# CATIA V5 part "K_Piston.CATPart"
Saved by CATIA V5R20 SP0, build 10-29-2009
Part number: Piston
Bounding box of the stored display mesh (mm): x -48 to -28, y 164.401 to 194.581, z -165.022 to -124.41
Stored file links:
  G:\Khaled_CFAO_2011\ST2M\ST2M_GR2\plakomicki\Khaled\CAD_ThinkMOTION\K_Piston.CATPart
  G:\Khaled_CFAO_2011\ST2M\ST2M_GR2\plakomicki\Khaled\CAD_ThinkMOTION\K_Jambe.CATProduct
  G:\Khaled_CFAO_2011\ST2M\ST2M_GR2\plakomicki\Khaled\plakomicki\Squelette_balancier.CATPart
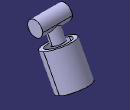
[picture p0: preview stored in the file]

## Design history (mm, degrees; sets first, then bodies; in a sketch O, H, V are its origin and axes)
Set1
  Plane1: linked copy from another document
  Point1: linked copy from another document
  Plane2: linked copy from another document
  Point2: linked copy from another document
Body1 (main body)
  Sketch1 on Plane1, origin (-38, 0, 0), H (0, 1, 0), V (0, 0, 1)
    circle A1 centre (169.4005, -129.4005) radius 5
    point P1 (169.4005, -129.4005)
    reference projected point E1 (169.4005, -129.4005) from Point1
    radius A1 = 5
    coincidence: P1 E1
  Pad1: profile Sketch1, direction (1, 0, 0), length 10, mirrored extent
  Sketch2 on Plane2, origin (0, 90.322, -171.1364), H (1, 0, 0), V (0, 0.8844, 0.4668)
    circle A1 centre (-38, 89.4164) radius 4
    point P1 (-38, 89.4164)
    reference projected point E1 (-38, 89.4164) from Point1
    radius A1 = 4
    coincidence: E1 P1
  Pad2: profile Sketch2, direction (0, 0.4668, -0.8844), length 12
  Sketch3 on end face of Pad2, origin (0, 95.9231, -181.7491), H (-1, 0, 0), V (0, 0.8844, 0.4668)
    circle A1 centre (38, 89.4164) radius 10
    point P1 (38, 89.4164)
    reference projected point E1 (38, 89.4164) from Point1
    circle A2 centre (38, 89.4164) radius 7.5
    radius A1 = 10
    radius A2 = 7.5
    coincidence: P1 E1
  Pad3: profile Sketch3, direction (0, 0.4668, -0.8844), length 23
